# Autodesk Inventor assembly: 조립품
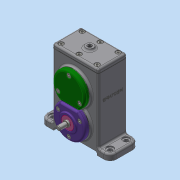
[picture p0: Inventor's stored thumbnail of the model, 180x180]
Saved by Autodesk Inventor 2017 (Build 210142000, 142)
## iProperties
Part Number: 조립품
Material: 일반
Document SubType Name: Assembly
Designer: 222
Author: 222
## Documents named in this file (24)
- C:\Users\222\Desktop\600506V1061\조립품.iam
- C:\Users\222\Desktop\600506V1061\Ű 4 x 4 x 12.ipt
- C:\Users\222\Desktop\600506V1061\Ű 5 x 5 x 12.ipt
- C:\Users\222\Desktop\600506V1061\개스킷 A.ipt
- C:\Users\222\Desktop\600506V1061\개스킷 B.ipt
- C:\Users\222\Desktop\600506V1061\개스킷 C.ipt
- C:\Users\222\Desktop\600506V1061\베어링 6001.ipt
- 베어링 6001.ipt
- C:\Users\222\Desktop\600506V1061\베어링 6002.ipt
- 베어링 6002.ipt
- C:\Users\222\Desktop\600506V1061\본체.ipt
- C:\Users\222\Desktop\600506V1061\볼트 M4.ipt
- C:\Users\222\Desktop\600506V1061\스퍼기어 A.ipt
- C:\Users\222\Desktop\600506V1061\스퍼기어 B.ipt
- C:\Users\222\Desktop\600506V1061\오일 실 10 20 7.ipt
- C:\Users\222\Desktop\600506V1061\오일 실 12 22 7.ipt
- C:\Users\222\Desktop\600506V1061\축 A.ipt
- C:\Users\222\Desktop\600506V1061\축 B.ipt
- C:\Users\222\Desktop\600506V1061\칼라.ipt
- C:\Users\222\Desktop\600506V1061\커버 A.ipt
- C:\Users\222\Desktop\600506V1061\커버 B.ipt
- C:\Users\222\Desktop\600506V1061\커버 C.ipt
- C:\Users\222\Desktop\600506V1061\커버 D.ipt
- C:\Users\222\Desktop\600506V1061\커버 E.ipt
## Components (7 placed, 5 different names)
1. Ű 4 x 4 x 12:1
2. Ű 5 x 5 x 12:1
3. 개스킷 A:1
4. 개스킷 B:1
5. 개스킷 C:1
6. 개스킷 B:2
7. 개스킷 B:3
